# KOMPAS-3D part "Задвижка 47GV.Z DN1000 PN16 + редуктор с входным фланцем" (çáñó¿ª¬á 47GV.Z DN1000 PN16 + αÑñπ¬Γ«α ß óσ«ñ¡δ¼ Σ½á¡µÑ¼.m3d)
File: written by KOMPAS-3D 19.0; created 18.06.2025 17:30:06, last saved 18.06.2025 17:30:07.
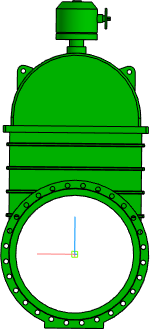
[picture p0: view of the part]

Document properties: Полное имя файла: Задвижка 47GV.Z DN1000 PN16 + редуктор с входным валом.a3d

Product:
- Part/product: Задвижка 47GV.Z DN1000 PN16 + редуктор с входным фланцем
    Масса: 4574.4
  - Body: Тело 1
      Масса: 4576.56

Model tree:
1. Операция без истории:1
